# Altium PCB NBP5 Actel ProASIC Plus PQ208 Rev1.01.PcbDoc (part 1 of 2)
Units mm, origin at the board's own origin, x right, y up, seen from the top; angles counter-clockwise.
Board outline 69 x 80.99 mm, 2 copper layers (Top Layer, Bottom Layer); 65 components, 193 nets, 558 pads, 171 vias.
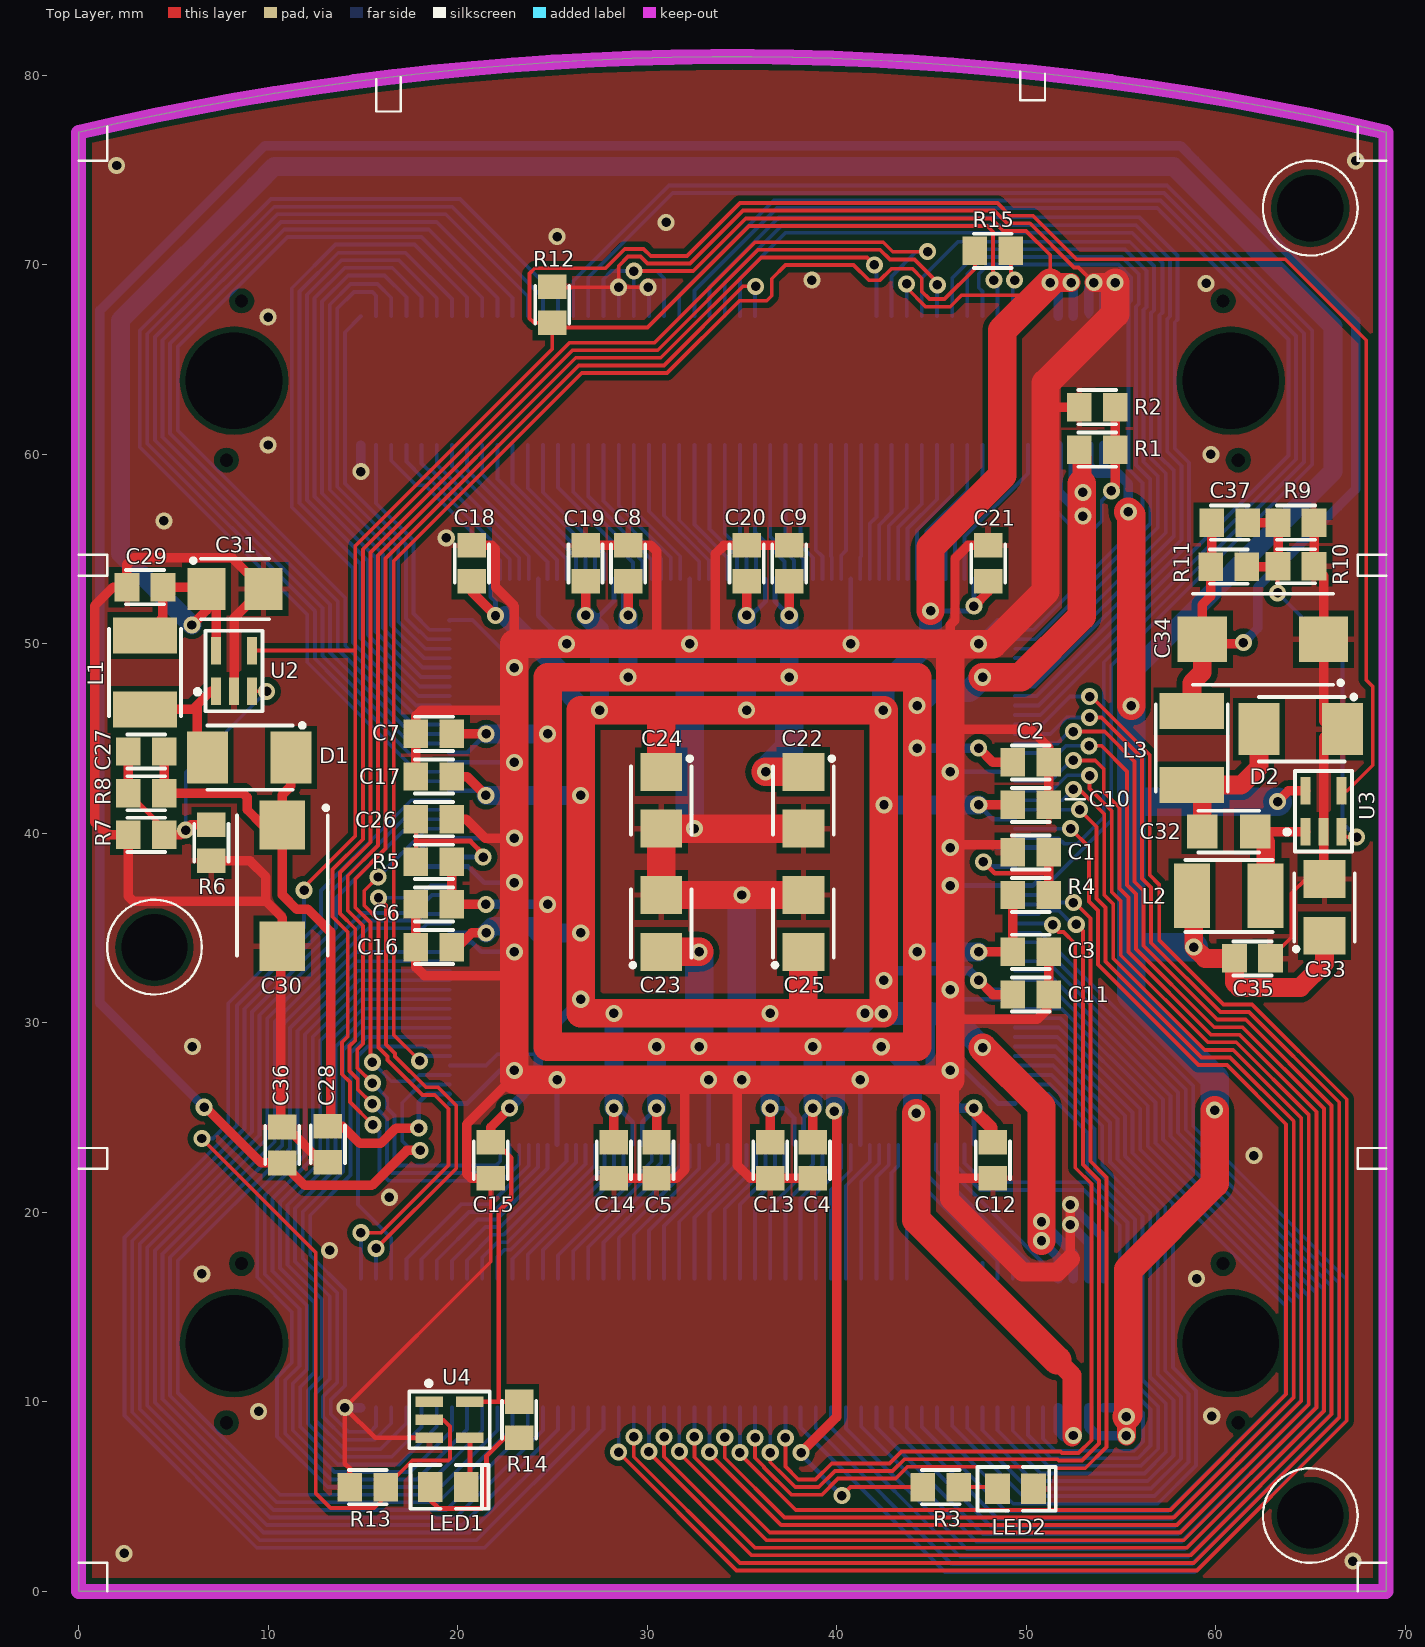
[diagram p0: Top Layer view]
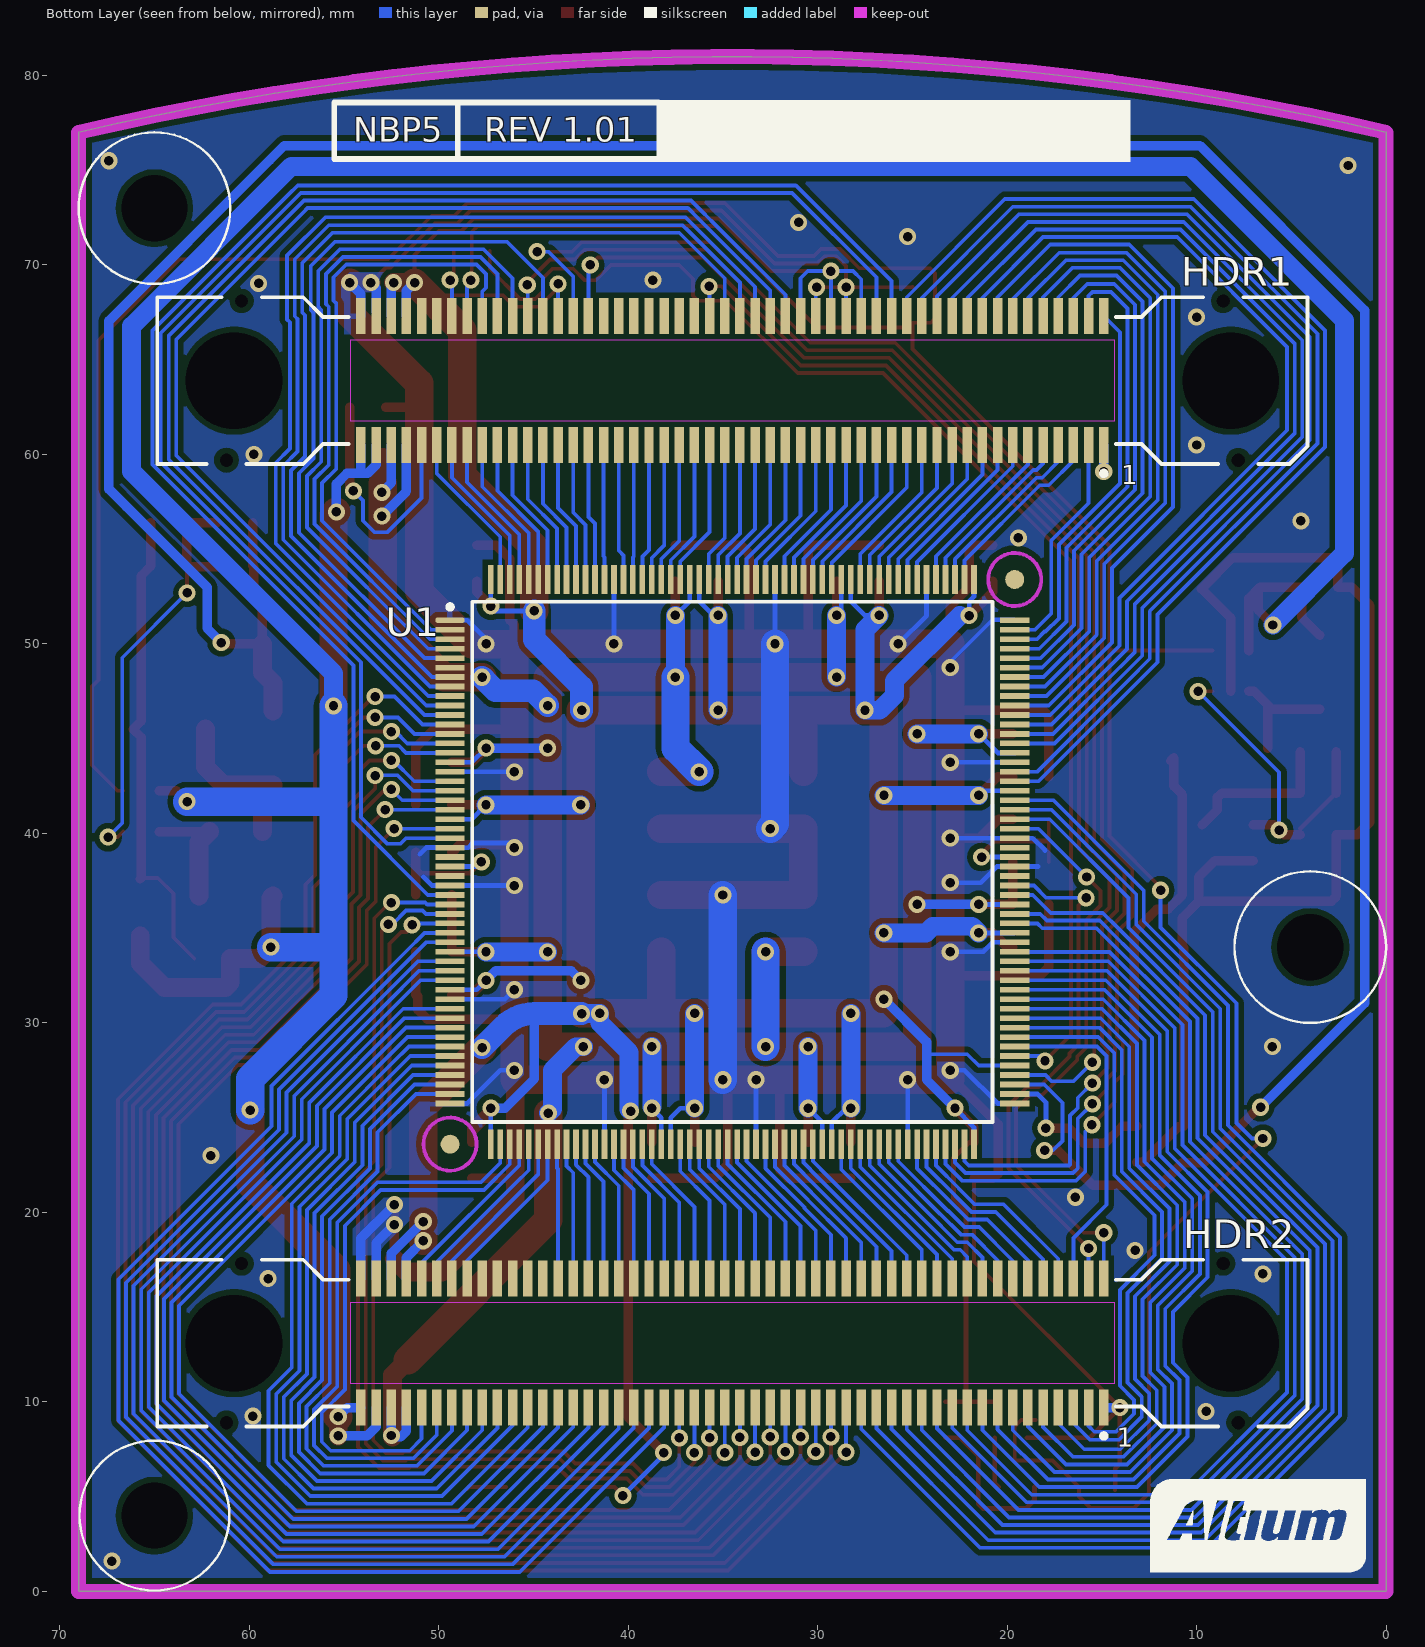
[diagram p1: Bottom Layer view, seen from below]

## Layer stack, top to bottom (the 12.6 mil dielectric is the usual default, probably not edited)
Top Layer: signal copper 0.0356
Dielectric: core 0.32, FR-4, Dk 4.8
Bottom Layer: signal copper 0.0356

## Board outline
0,0 0.001,77 cw(c34.5,-69.801) 69,77 69,0

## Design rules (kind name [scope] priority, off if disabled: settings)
Clearance Clearance_Polygons [InPolygon] p1: gap=0.3
Clearance [All] p2: gap=0.2
ComponentClearance [All] p1: gap=0.2 collisioncheckmode=3 verticalgap=0.254 showdistances=FALSE
FabricationTestPointUsage TestPointUsage [All] p1 off: valid=0 allowmultiple=FALSE
FabricationTestpoint Testpoint [All] p1 off: side=3 testpointundercomponent=TRUE minsize=1.016 maxsize=2.54 preferedsize=1.524 minholesize=0 maxholesize=1.016 preferedholesize=0.813 testpointgrid=0.025 allowsidetop=TRUE allowsidebottom=TRUE usegrid=TRUE gridtolerance=0
HoleSize [All] p1: absolutevalues=TRUE maxlimit=5.2 minlimit=0.25 maxpercent=80.000 minpercent=20.000
PlaneClearance [All] p1: clearance=0.5
PlaneConnect [All] p1: planeconnectstyle=Relief reliefexpansion=0.5 reliefentries=4 reliefconductorwidth=0.25 reliefairgap=0.25
PolygonConnect [All] p1: connectstyle=Relief reliefconductorwidth=0.3 reliefentries=4 polygonreliefangle="90 Angle"
RoomDefinition Actel_APA_1_01 [InComponentClass('Actel_APA_1_01')] p1 off: confinementstyle=ConfineIn formatcopy=TRUE lockcomponents=FALSE outline 3.9,7.7 3.9,69.1 65.2,69.1 65.2,7.7 51.98,4 21.98,4 17.25,4
RoutingVias [All] p1: holewidth=0.5 width=0.9 viastyle="Through Hole" minholewidth=0.3 minwidth=0.6 maxholewidth=0.5 maxwidth=0.9
SMDNeckDown [All] p1: percent=100.000
SilkscreenOverComponentPads [All] p1: minsilkscreentomaskgap=0.254
SolderMaskExpansion SolderMaskExpansion_Vias [IsVia] p1: expansion=-0.2
SolderMaskExpansion [All] p2: expansion=0.1
Width [All] p1: maxlimit=1.5 minlimit=0.2 preferedwidth=0.5
21 further rules are at their usual default settings.

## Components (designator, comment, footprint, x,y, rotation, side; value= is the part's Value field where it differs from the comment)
C1 "0.1uF" CC2012-0805 50.25,39 r180 top
C2 "0.1uF" CC2012-0805 50.25,43.75 r180 top
C3 "0.1uF" CC2012-0805 50.25,33.75 r180 top
C4 "0.1uF" CC2012-0805 38.75,22.75 r90 top
C5 "0.1uF" CC2012-0805 30.5,22.75 r90 top
C6 "0.1uF" CC2012-0805 18.75,36.25 r0 top
C7 "0.1uF" CC2012-0805 18.75,45.25 r0 top
C8 "0.1uF" CC2012-0805 29,54.25 r270 top
C9 "0.1uF" CC2012-0805 37.5,54.25 r270 top
C10 "0.1uF" CC2012-0805 50.25,41.5 r0 top
C11 "0.1uF" CC2012-0805 50.25,31.5 r180 top
C12 "0.1uF" CC2012-0805 48.25,22.75 r90 top
C13 "0.1uF" CC2012-0805 36.5,22.75 r90 top
C14 "0.1uF" CC2012-0805 28.25,22.75 r90 top
C15 "0.1uF" CC2012-0805 21.75,22.75 r90 top
C16 "0.1uF" CC2012-0805 18.75,34 r0 top
C17 "0.1uF" CC2012-0805 18.75,43 r0 top
C18 "0.1uF" CC2012-0805 20.75,54.25 r270 top
C19 "0.1uF" CC2012-0805 26.75,54.25 r270 top
C20 "0.1uF" CC2012-0805 35.25,54.25 r270 top
C21 "0.1uF" CC2012-0805 48,54.25 r270 top
C22 "10uF" MCCT-B 38.25,41.75 r270 top
C23 "10uF" MCCT-B 30.75,35.25 r90 top
C24 "10uF" MCCT-B 30.75,41.75 r270 top
C25 "10uF" MCCT-B 38.25,35.25 r90 top
C26 "0.1uF" CC2012-0805 18.75,40.75 r0 top
C27 "10pF" CC2012-0805 3.575,44.325 r180 top
C28 "0.1uF" CC2012-0805 13.15,23.6 r270 top
C29 "0.1uF" CC2012-0805 3.5,53 r180 top
C30 "22uF 25V" MCCT-D 10.75,37.25 r270 top
C31 "10uF" MCCT-B 8.25,52.9 r0 top
C32 "1uF 25V" CC3216-1206 60.7,40.1 r180 top
C33 "10uF" MCCT-B 65.75,36.1 r90 top
C34 "22uF" MCCT-D 62.5,50.25 r180 top
C35 "0.1uF" CC2012-0805 61.95,33.4 r0 top
C36 "0.1uF" CC2012-0805 10.75,23.559 r90 top
C37 "10pF" CC2012-0805 60.75,56.4 r0 top
D1 "MBRS140T3" 403A 9,44 r0 top
D2 "MBRS140T3" 403A 64.5,45.5 r0 top
HDR1 "54075-1009" 54075 34.5,63.9 r0 bottom locked
HDR2 "54075-1009" 54075 34.5,13.1 r0 bottom locked
L1 "10uH" CC4532-1812 3.5,48.5 r270 top
L2 "10uH" CC4532-1812 60.7,36.7 r0 top
L3 "10uH" CC4532-1812 58.75,44.5 r90 top
LED1 "HSMG-C170" "SMD _LED"#1 19.5,5.5 r180 top locked
LED2 "HSMH-C170" "SMD _LED"#2 49.442,5.408 r180 top locked
R1 "82R/1%" CC2012-0805 53.75,60.25 r0 top
R2 "680R/1%" CC2012-0805 53.75,62.5 r180 top
R3 "270R" CC2012-0805 45.5,5.5 r0 top
R4 "1R" CC2012-0805 50.25,36.75 r0 top
R5 "1R" CC2012-0805 18.75,38.5 r180 top
R6 "100K" CC2012-0805 7,39.5 r270 top
R7 "18K" CC2012-0805 3.575,39.925 r180 top
R8 "180K" CC2012-0805 3.575,42.125 r180 top
R9 "6k8" CC2012-0805 64.25,56.4 r0 top
R10 "1K2" CC2012-0805 64.25,54.1 r0 top
R11 "10K" CC2012-0805 60.7,54.075 r0 top
R12 "470R" CC2012-0805 25,67.9 r90 top
R13 "1K" CC2012-0805 15.25,5.5 r0 top
R14 "270R" CC2012-0805 23.25,9.05 r90 top
R15 "33R" CC2012-0805 48.25,70.75 r180 top
U1 "APA750-PQ208I" F-QFP28X28-G208/P.5N 34.49,38.49 r180 bottom locked
U2 "LT1930" SO-G5/P.95 7.25,47.5 r90 top
U3 "LT1931" SO-G5/P.95 64.75,40.1 r90 top
U4 "SN74LVC1G04DBV" SO-G5/P.95 18.5,10 r0 top

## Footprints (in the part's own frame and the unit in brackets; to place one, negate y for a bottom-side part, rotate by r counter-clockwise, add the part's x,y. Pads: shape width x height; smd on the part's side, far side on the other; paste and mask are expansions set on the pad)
403A [mm]
  rect 2.159x2.743 smd: 1(-2.2,0) 2(2.2,0)
  silkscreen extent -2.2,-1.7 2.9,1.8
54075 [mm] "Connector; Docking Station, Receptacle; 100 Position; Vertical"
  rect 0.5x1.9 smd: 1(-19.6,3.4) 2(-19.6,-3.4) 3(-18.8,3.4) 4(-18.8,-3.4) 5(-18,3.4) 6(-18,-3.4) 7(-17.2,3.4) 8(-17.2,-3.4) 9(-16.4,3.4) 10(-16.4,-3.4) 11(-15.6,3.4) 12(-15.6,-3.4) 13(-14.8,3.4) 14(-14.8,-3.4) 15(-14,3.4) 16(-14,-3.4) 17(-13.2,3.4) 18(-13.2,-3.4) 19(-12.4,3.4) 20(-12.4,-3.4) 21(-11.6,3.4) 22(-11.6,-3.4) 23(-10.8,3.4) 24(-10.8,-3.4) 25(-10,3.4) 26(-10,-3.4) 27(-9.2,3.4) 28(-9.2,-3.4) 29(-8.4,3.4) 30(-8.4,-3.4) 31(-7.6,3.4) 32(-7.6,-3.4) 33(-6.8,3.4) 34(-6.8,-3.4) 35(-6,3.4) 36(-6,-3.4) 37(-5.2,3.4) 38(-5.2,-3.4) 39(-4.4,3.4) 40(-4.4,-3.4) 41(-3.6,3.4) 42(-3.6,-3.4) 43(-2.8,3.4) 44(-2.8,-3.4) 45(-2,3.4) 46(-2,-3.4) 47(-1.2,3.4) 48(-1.2,-3.4) 49(-0.4,3.4) 50(-0.4,-3.4) 51(0.4,3.4) 52(0.4,-3.4) 53(1.2,3.4) 54(1.2,-3.4) 55(2,3.4) 56(2,-3.4) 57(2.8,3.4) 58(2.8,-3.4) 59(3.6,3.4) 60(3.6,-3.4) 61(4.4,3.4) 62(4.4,-3.4) 63(5.2,3.4) 64(5.2,-3.4) 65(6,3.4) 66(6,-3.4) 67(6.8,3.4) 68(6.8,-3.4) 69(7.6,3.4) 70(7.6,-3.4) 71(8.4,3.4) 72(8.4,-3.4) 73(9.2,3.4) 74(9.2,-3.4) 75(10,3.4) 76(10,-3.4) 77(10.8,3.4) 78(10.8,-3.4) 79(11.6,3.4) 80(11.6,-3.4) 81(12.4,3.4) 82(12.4,-3.4) 83(13.2,3.4) 84(13.2,-3.4) 85(14,3.4) 86(14,-3.4) 87(14.8,3.4) 88(14.8,-3.4) 89(15.6,3.4) 90(15.6,-3.4) 91(16.4,3.4) 92(16.4,-3.4) 93(17.2,3.4) 94(17.2,-3.4) 95(18,3.4) 96(18,-3.4) 97(18.8,3.4) 98(18.8,-3.4) 99(19.6,3.4) 100(19.6,-3.4)
  round 0.5 hole 0.7 unplated: MH1(-26.7,4.2) MH2(-25.9,-4.2) MH3(26.7,4.2) MH4(25.9,-4.2)
  round 4.8 hole 5.1 unplated: MH5(-26.3,0) MH6(26.3,0)
  Top Layer keep-out region: -20.15,2.15 20.15,2.15 20.15,-2.15 -20.15,-2.15
  silkscreen extent -30.35,-4.4 30.35,5.02
CC2012-0805 [mm]
  rect 1.3x1.5 smd: 1(-0.95,0.003) 2(0.95,0.003)
  silkscreen extent -1,-0.9 1,0.9
CC3216-1206 [mm]
  rect 1.6x1.8 smd: 1(-1.4,0) 2(1.4,0)
  silkscreen extent -1.6,-1.1 1.6,1.1
CC4532-1812 [mm]
  rect 1.9x3.4 smd: 1(-1.95,0) 2(1.95,0)
  silkscreen extent -2.3,-1.9 2.3,1.9
F-QFP28X28-G208/P.5N [mm]
  oval 1.55x0.3 smd: 1(-14.91,12.761)
  rect 1.55x0.3 smd: 2(-14.91,12.261) 3(-14.91,11.761) 4(-14.91,11.261) 5(-14.91,10.761) 6(-14.91,10.261) 7(-14.91,9.761) 8(-14.91,9.261) 9(-14.91,8.761) 10(-14.91,8.261) 11(-14.91,7.761) 12(-14.91,7.261) 13(-14.91,6.761) 14(-14.91,6.261) 15(-14.91,5.761) 16(-14.91,5.261) 17(-14.91,4.761) 18(-14.91,4.261) 19(-14.91,3.761) 20(-14.91,3.261) 21(-14.91,2.761) 22(-14.91,2.261) 23(-14.91,1.761) 24(-14.91,1.261) 25(-14.91,0.761) 26(-14.91,0.261) 27(-14.91,-0.239) 28(-14.91,-0.739) 29(-14.91,-1.239) 30(-14.91,-1.739) 31(-14.91,-2.239) 32(-14.91,-2.739) 33(-14.91,-3.239) 34(-14.91,-3.739) 35(-14.91,-4.239) 36(-14.91,-4.739) 37(-14.91,-5.239) 38(-14.91,-5.739) 39(-14.91,-6.239) 40(-14.91,-6.739) 41(-14.91,-7.239) 42(-14.91,-7.739) 43(-14.91,-8.239) 44(-14.91,-8.739) 45(-14.91,-9.239) 46(-14.91,-9.739) 47(-14.91,-10.239) 48(-14.91,-10.739) 49(-14.91,-11.239) 50(-14.91,-11.739) 51(-14.91,-12.239) 52(-14.91,-12.739) 105(14.89,-12.739) 106(14.89,-12.239) 107(14.89,-11.739) 108(14.89,-11.239) 109(14.89,-10.739) 110(14.89,-10.239) 111(14.89,-9.739) 112(14.89,-9.239) 113(14.89,-8.739) 114(14.89,-8.239) 115(14.89,-7.739) 116(14.89,-7.239) 117(14.89,-6.739) 118(14.89,-6.239) 119(14.89,-5.739) 120(14.89,-5.239) 121(14.89,-4.739) 122(14.89,-4.239) 123(14.89,-3.739) 124(14.89,-3.239) 125(14.89,-2.739) 126(14.89,-2.239) 127(14.89,-1.739) 128(14.89,-1.239) 129(14.89,-0.739) 130(14.89,-0.239) 131(14.89,0.261) 132(14.89,0.761) 133(14.89,1.261) 134(14.89,1.761) 135(14.89,2.261) 136(14.89,2.761) 137(14.89,3.261) 138(14.89,3.761) 139(14.89,4.261) 140(14.89,4.761) 141(14.89,5.261) 142(14.89,5.761) 143(14.89,6.261) 144(14.89,6.761) 145(14.89,7.261) 146(14.89,7.761) 147(14.89,8.261) 148(14.89,8.761) 149(14.89,9.261) 150(14.89,9.761) 151(14.89,10.261) 152(14.89,10.761) 153(14.89,11.261) 154(14.89,11.761) 155(14.89,12.261) 156(14.89,12.761)
  rect 0.3x1.55 smd: 53(-12.76,-14.889) 54(-12.26,-14.889) 55(-11.76,-14.889) 56(-11.26,-14.889) 57(-10.76,-14.889) 58(-10.26,-14.889) 59(-9.76,-14.889) 60(-9.26,-14.889) 61(-8.76,-14.889) 62(-8.26,-14.889) 63(-7.76,-14.889) 64(-7.26,-14.889) 65(-6.76,-14.889) 66(-6.26,-14.889) 67(-5.76,-14.889) 68(-5.26,-14.889) 69(-4.76,-14.889) 70(-4.26,-14.889) 71(-3.76,-14.889) 72(-3.26,-14.889) 73(-2.76,-14.889) 74(-2.26,-14.889) 75(-1.76,-14.889) 76(-1.26,-14.889) 77(-0.76,-14.889) 78(-0.26,-14.889) 79(0.24,-14.889) 80(0.74,-14.889) 81(1.24,-14.889) 82(1.74,-14.889) 83(2.24,-14.889) 84(2.74,-14.889) 85(3.24,-14.889) 86(3.74,-14.889) 87(4.24,-14.889) 88(4.74,-14.889) 89(5.24,-14.889) 90(5.74,-14.889) 91(6.24,-14.889) 92(6.74,-14.889) 93(7.24,-14.889) 94(7.74,-14.889) 95(8.24,-14.889) 96(8.74,-14.889) 97(9.24,-14.889) 98(9.74,-14.889) 99(10.24,-14.889) 100(10.74,-14.889) 101(11.24,-14.889) 102(11.74,-14.889) 103(12.24,-14.889) 104(12.74,-14.889) 157(12.74,14.911) 158(12.24,14.911) 159(11.74,14.911) 160(11.24,14.911) 161(10.74,14.911) 162(10.24,14.911) 163(9.74,14.911) 164(9.24,14.911) 165(8.74,14.911) 166(8.24,14.911) 167(7.74,14.911) 168(7.24,14.911) 169(6.74,14.911) 170(6.24,14.911) 171(5.74,14.911) 172(5.24,14.911) 173(4.74,14.911) 174(4.24,14.911) 175(3.74,14.911) 176(3.24,14.911) 177(2.74,14.911) 178(2.24,14.911) 179(1.74,14.911) 180(1.24,14.911) 181(0.74,14.911) 182(0.24,14.911) 183(-0.26,14.911) 184(-0.76,14.911) 185(-1.26,14.911) 186(-1.76,14.911) 187(-2.26,14.911) 188(-2.76,14.911) 189(-3.26,14.911) 190(-3.76,14.911) 191(-4.26,14.911) 192(-4.76,14.911) 193(-5.26,14.911) 194(-5.76,14.911) 195(-6.26,14.911) 196(-6.76,14.911) 197(-7.26,14.911) 198(-7.76,14.911) 199(-8.26,14.911) 200(-8.76,14.911) 201(-9.26,14.911) 202(-9.76,14.911) 203(-10.26,14.911) 204(-10.76,14.911) 205(-11.26,14.911) 206(-11.76,14.911) 207(-12.26,14.911) 208(-12.76,14.911)
  round 1 smd mask+1: FID1(-14.91,-14.889) FID2(14.89,14.911)
  Top Layer keep-out circle w0.2: c14.89,14.911 r1.4
  Top Layer keep-out circle w0.2: c-14.91,-14.889 r1.4
  silkscreen extent -15.03,-13.71 13.72,13.74
MCCT-B [mm]
  rect 2x2.2 smd: 1(-1.5,0) 2(1.5,0)
  silkscreen extent -2.3,-1.6 1.8,1.6
MCCT-D [mm]
  rect 2.6x2.4 smd: 1(-3.2,0) 2(3.2,0)
  silkscreen extent -4.2,-2.4 3.7,2.4
"SMD _LED"#1 [mm]
  rect 1.3x1.6 smd: 1(0.943,-0.012) 2(-0.957,-0.012)
  silkscreen extent -2.14,-1.16 1.99,1.14
"SMD _LED"#2 [mm]
  rect 1.3x1.6 smd: 1(0.95,0) 2(-0.95,0)
  silkscreen extent -2.13,-1.15 2,1.15
SO-G5/P.95 [mm]
  rect 1.45x0.55 smd: 1(0,0) 2(0,-0.95) 3(0,-1.9) 4(2.15,-1.9) 5(2.15,0)
  silkscreen extent -1.05,-2.45 3.2,1.1

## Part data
C1 C2 C3 C4 C5 C6 C7 C8 C9 C10 C11 C12 C13 C14 C15 C16 C17 C18 C19 C20 C21 C26 C27 C28 C29 C32 C35 C36 C37: library part CAP, "Capacitor"
C22 C23 C24 C25 C30 C31 C33 C34: library part CAP_POLAR, "Polar Capacitor"
D1 D2: library part Shottky, "Shottky Diode"
HDR1 HDR2: "Board-to-Board, Docking Station, 0.80mm (.031\") Pitch, Shielded Receptacle, Vertical, Ultra Low Profile, SMT"
L1 L2 L3: library part INDUCTOR, "Inductor"
LED1 LED2: library part HSMX-C670, "Typical RED GaAs SMD LED Agilent make"
R1 R2 R3 R4 R5 R6 R7 R8 R9 R10 R11 R12 R13 R14 R15: library part RES, "Resistor"
U1: "ProASICPlus APA750 Flash FPGA, 156 User IOs, 208-Pin PQFP, Speed Grade Standard, Industrial Grade"
U2 U3: "Switching Regulator"
U4: library part SN74AHC1G04DBVR

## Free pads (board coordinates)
  round 3.2 hole 3.5 unplated: LP(4,34) LP(65,4) LP(65,73)

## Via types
v1: diameter 0.9, hole 0.5, Top Layer to Bottom Layer, tented bottom, 171 vias

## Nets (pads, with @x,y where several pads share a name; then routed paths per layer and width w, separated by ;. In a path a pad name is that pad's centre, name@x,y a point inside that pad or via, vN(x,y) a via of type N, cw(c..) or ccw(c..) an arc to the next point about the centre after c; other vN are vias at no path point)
5V: C29.1 C31.1 C33.1 C35.1 HDR1.97 HDR1.99 HDR2.97 HDR2.99 L1.1 L2.1 U2.5 U3.5 | length 213.5
  Top Layer w0.5: L1.1@3.5,50.45 4.45,51.4 C29.1@4.45,52.997 6.653,52.997 7.25,52.4 U2.5@7.25,49.65 ; v1(5.975,51) 6.75,51.775 C31.1@6.75,52.9 ; v1(63.275,41.675) 63.85,42.25 U3.5@64.75,42.25
  Top Layer w1: v1(55.3,8.2) v1(55.3,9.225) ; L2.1@58.75,36.7 58.85,36.6 v1(58.85,34) 59.447,33.403 C35.1@61,33.403 61,32.125 61.25,31.875 64.475,31.875 65.75,33.15 C33.1@65.75,34.6
  Top Layer w1.5: v1(55.3,9.225) 55.4,9.325 55.4,16.975 59.95,21.525 v1(59.95,25.4) ; v1(55.4,56.975) 55.55,56.825 v1(55.55,46.735)
  Bottom Layer w0.5: HDR2.97@53.3,9.7 53.3,8.675 53.775,8.2 v1(55.3,8.2) ; HDR1.97@53.3,60.5 53.3,59.45 53.75,59 54.85,59 55.4,58.45 v1(55.4,56.975) ; HDR2.99@54.1,9.7 54.825,9.7 v1(55.3,9.225) ; HDR1.99@54.1,60.5 54.1,59.125 54.225,59
  Bottom Layer w1: v1(5.975,51) 2.2,54.775 2.2,67.075 9.315,74.19 10.325,75.2 57.775,75.2 66.2,66.775 66.2,59.1 55.55,48.45 v1(55.55,46.735)
  Bottom Layer w1.5: 55.55,34 v1(58.85,34) ; v1(55.55,46.735) 55.55,31.45 59.95,27.05 v1(59.95,25.4) ; 55.725,41.675 v1(63.275,41.675)
AUDIO_SPI_CSN: HDR1.11 U1.161 | length 9.1
  Bottom Layer w0.2: HDR1.11@18.9,60.5 18.9,59.475 23.75,54.625 U1.161@23.75,53.425
AVDD1: C1.1 R4.2 U1.27 | length 8.1
  Top Layer w0.25: v1(47.75,38.5) 48.35,37.9 50.9,37.9 51,38 C1.1@51.35,38.375
  Top Layer w0.5: R4.2@51.2,36.753 C1.1@51.2,38.997
  Bottom Layer w0.25: v1(47.75,38.5) 48,38.25 U1.27@49.425,38.25
AVDD2: C26.1 R5.2 U1.131 | length 8
  Top Layer w0.2: R5.2@17.8,38.497 C26.1@17.8,40.753
  Top Layer w0.25: 17.8,39.6 20.675,39.6 21.1,39.175 21.1,39 v1(21.35,38.75)
  Bottom Layer w0.25: U1.131@19.6,38.751 v1(21.35,38.75)
BLUE0: HDR1.14 U1.148 | length 36.4
  Bottom Layer w0.2: U1.148@19.575,47.25 17.925,47.25 14.869,50.306 14.869,54.215 11.65,57.434 11.65,68.6 13.7,70.65 17.25,70.65 19.7,68.2 HDR1.14@19.7,67.3
BLUE1: HDR1.16 U1.147 | length 38.9
  Bottom Layer w0.2: U1.147@19.575,46.75 17.8,46.75 14.469,50.081 14.469,54.006 11.25,57.225 11.25,68.775 13.55,71.075 17.725,71.075 20.5,68.3 HDR1.16@20.5,67.3
BOC_CTS: HDR1.13 U1.163 | length 9.2
  Bottom Layer w0.2: HDR1.13@19.7,60.5 19.7,59.375 24.75,54.325 U1.163@24.75,53.425
BOC_RTS: HDR1.17 U1.165 | length 8.9
  Bottom Layer w0.2: HDR1.17@21.3,60.5 21.3,58.941 25.75,54.491 U1.165@25.75,53.425
BOC_RX: HDR1.19 U1.166 | length 8.8
  Bottom Layer w0.2: HDR1.19@22.1,60.5 22.1,58.706 26.25,54.556 U1.166@26.25,53.425
BOC_TX: HDR1.15 U1.164 | length 9
  Bottom Layer w0.2: HDR1.15@20.5,60.5 20.5,59.175 25.25,54.425 U1.164@25.25,53.425
BUZZER: HDR2.24 U1.91 | length 9
  Bottom Layer w0.2: HDR2.24@23.7,16.5 23.7,17.775 28.25,22.325 U1.91@28.25,23.575
CAN_RXD: HDR1.4 U1.153 | length 24.7
  Bottom Layer w0.2: HDR1.4@15.7,67.3 15.7,68.375 15.5,68.575 14.525,68.575 13.65,67.7 13.65,58.3 16.869,55.081 16.869,51.181 18.3,49.75 U1.153@19.575,49.75
CAN_TXD: HDR1.2 U1.154 | length 20.4
  Bottom Layer w0.2: HDR1.2@14.9,67.3 14.05,66.45 14.05,58.475 17.269,55.256 17.269,51.346 17.966,50.65 18.025,50.65 18.425,50.25 U1.154@19.575,50.25
FPGA_AUX0: HDR1.86 R12.1 R13.2 U2.4 U3.4 U4.2 | length 197.7
  Top Layer w0.2: v1(6.5,23.9) 12.508,17.892 12.508,5.192 13.3,4.4 15.6,4.4 16.2,5 R13.2@16.2,5.503 17.605,6.907 19.507,6.907 19.6,7 19.6,8.7 19.25,9.05 U4.2@18.5,9.05 ; U2.4@9.15,49.65 14.55,49.65 ; v1(11.9,37) 11.9,37.163 14.6,39.863 14.6,55.166 24.997,65.563 R12.1@24.997,66.95 ; v1@48.25,69.25 v1(48.3,69.2) ; 48.25,69.65 48.25,71.75 47.95,72.05 35.375,72.05 30.025,66.7 25.247,66.7 R12.1@24.997,66.95 ; U3.4@66.65,42.25 66.95,42.25 68.3,43.6 68.3,47.75 67.95,48.1 67.95,66.025 63.675,70.3 52.666,70.3 50.366,72.6 49.166,72.6 48.491,73.275 34.9,73.275 32.1,70.475 30.191,70.475 29.816,70.85 28.825,70.85 27.8,69.825 24.075,69.825 23.8,69.55 23.8,67.175 24.025,66.95 R12.1@24.997,66.95
  Bottom Layer w0.2: v1(6.5,23.9) 7.084,23.9 7.9,24.716 7.9,31.041 11.9,35.041 v1(11.9,37) ; v1(48.3,69.2) 48.5,69 HDR1.86@48.5,67.3 48.5,68.3
FPGA_AUX1: HDR1.88 R15.1 | length 7.1
  Top Layer w0.2: v1@49.1,69.2 49.2,69.3 R15.1@49.2,70.747 49.2,69.4 v1(49.4,69.2)
  Bottom Layer w0.2: v1@49.1,69.2 49.3,69 HDR1.88@49.3,67.3 49.3,69.1 v1(49.4,69.2)
FPGA_AUX2: HDR1.90
FPGA_AUX3: HDR1.92
FPGA_CCLK: HDR1.66
FPGA_CLK: HDR2.2 U1.134 | length 31.1
  Top Layer w0.2: v1(14.9,18.925) 15.959,18.925 19.525,22.491 19.525,25.469 18.794,26.2 18.15,26.2 16.3,28.05 16.3,28.225 15.825,28.7 15.825,35.438 15.075,36.188 15.075,36.975 v1(15.8,37.7)
  Bottom Layer w0.2: HDR2.2@14.9,16.5 v1(14.9,18.925) ; v1(15.8,37.7) 18.351,40.251 U1.134@19.6,40.251
FPGA_CLK_1: HDR1.30 U1.30 | length 83.1
  Bottom Layer w0.2: HDR1.30@26.1,67.3 26.1,69.15 30.432,73.482 31.15,74.2 57.441,74.2 57.944,73.696 57.954,73.696 65.1,66.55 65.1,59.469 54.5,48.869 54.5,40.675 50.575,36.75 U1.30@49.425,36.75
FPGA_CLK_2: HDR1.32 U1.24 | length 80
  Bottom Layer w0.2: HDR1.32@26.9,67.3 26.9,69.35 31.35,73.8 57.275,73.8 64.675,66.4 64.675,59.609 54.1,49.034 54.1,40.85 52.7,39.45 52.025,39.45 51.725,39.75 U1.24@49.425,39.75
FPGA_DIN: HDR1.64
FPGA_INIT: HDR1.68
FPGA_M0: HDR1.60
FPGA_M1: HDR1.58
FPGA_M2: HDR1.56
FPGA_PROGRAM: HDR1.62
FPGA_RCK: R15.2 U1.110 | length 69.6
  Top Layer w0.2: v1(18,28) 16.625,29.375 16.625,54.362 26.556,64.294 31.05,64.294 34.872,68.116 36.316,68.116 36.575,68.375 36.575,69.275 37.3,70 40.9,70 41.7,69.2 42.3,69.2 42.9,69.8 44,69.8 44.5,69.3 44.5,68.6 44.9,68.2 45.7,68.2 47.3,69.8 R15.2@47.3,70.747
  Bottom Layer w0.2: v1(18,28) 18.251,28.251 U1.110@19.6,28.251
FPGA_TCK: HDR1.72 U1.101 | length 85
  Top Layer w0.2: v1(15.525,24.625) 14.319,25.831 14.319,26.874 13.9,27.294 13.9,28.975 14.2,29.275 14.2,34.8 13.4,35.6 13.4,38.097 15,39.697 15,55 25.9,65.9 30.394,65.9 35.694,71.2 42.466,71.2 42.966,70.7 v1(44.8,70.7)
  Bottom Layer w0.2: v1(15.525,24.625) 15.875,24.275 15.875,22.15 16.35,21.675 22.375,21.675 23.25,22.55 U1.101@23.25,23.575 ; HDR1.72@42.9,67.3 42.9,69.4 44.2,70.7 v1(44.8,70.7)
FPGA_TDI: HDR1.78 U1.102 | length 81.5
  Top Layer w0.2: v1(15.5,25.725) 14.725,26.5 14.725,27.034 14.3,27.459 14.3,28.775 14.6,29.075 14.6,34.966 13.8,35.766 13.8,37.931 15.4,39.531 15.4,54.834 26.066,65.5 30.559,65.5 35.859,70.8 42.3,70.8 42.817,70.283 44.117,70.283 45.325,69.075 v1(45.325,68.95) v1@45.125,68.75
  Bottom Layer w0.2: v1(15.5,25.725) 16.275,24.95 16.275,22.325 16.525,22.075 22.2,22.075 22.75,22.625 U1.102@22.75,23.575 ; HDR1.78@45.3,67.3 45.3,68.925 v1(45.325,68.95)
FPGA_TDO: HDR1.54 U1.108 | length 59.3
  Top Layer w0.2: v1(15.5,27.925) 15.4,28.025 15.4,35.297 14.6,36.097 14.6,37.6 16.2,39.2 16.2,54.503 26.397,64.7 30.891,64.7 35.066,68.875 v1(35.725,68.875)
  Bottom Layer w0.2: v1(15.5,27.925) 16.5,26.925 17.65,26.925 17.975,27.25 U1.108@19.575,27.25 ; HDR1.54@35.7,67.3 v1@35.7,68.85
FPGA_TMS: HDR1.70 U1.103 | length 76.5
  Top Layer w0.2: v1(15.5,26.825) 14.7,27.625 14.7,28.6 15,28.9 15,35.131 14.2,35.931 14.2,37.766 15.8,39.366 15.8,54.669 26.231,65.1 30.725,65.1 36.025,70.4 41.6,70.4 v1(42,70)
  Bottom Layer w0.2: v1(15.5,26.825) 16.275,26.05 16.275,25.516 16.675,25.116 16.675,22.525 16.725,22.475 22.025,22.475 22.25,22.7 U1.103@22.25,23.575 ; v1(42,70) 42.1,70.1 HDR1.70@42.1,67.3
GND: C1.2 C2.1 C3.1 C4.1 C5.1 C6.1 C7.1 C8.1 C9.1 C10.2 C11.1 C12.1 C13.1 C14.1 C15.1 C16.1 C17.1 C18.1 C19.1 C20.1 C21.1 C22.2 C23.2 C24.2 C25.2 C26.2 C28.2 C29.2 C30.2 C31.2 C33.2 C34.1 C35.2 C36.2 D2.2 HDR1.1 HDR1.36 HDR1.40 HDR1.98 HDR1.100 HDR2.1 HDR2.98 HDR2.100 LED2.2 R2.2 R6.2 R7.2 R9.2 R10.2 R12.2 R13.1 U1.1 U1.17 U1.25 U1.29 U1.41 U1.52 U1.65 U1.81 U1.97 U1.105 U1.122 U1.130 U1.133 U1.141 U1.156 U1.162 U1.178 U1.195 U2.2 U3.2 U4.3 | length 509.2
  Top Layer w0.2: v1(14.05,9.7) 21.747,17.397 C15.1@21.747,21.8 ; R13.1@14.3,5.35 R13.1@14.3,5.503 ; R12.2@24.997,68.85 25.022,68.825 v1(30.05,68.825) ; v1(28.5,68.825) 28.5,69.95 29,70.45 29.65,70.45 30.025,70.075 32.269,70.075 35.069,72.875 48.325,72.875 49,72.2 50.2,72.2 52.525,69.875 52.775,69.875 v1(53.575,69.075) ; C35.2@62.9,33.403 64,34.503 64,36.825 64.825,37.65 C33.2@65.7,37.65
  Top Layer w0.25: R13.1@14.3,5.503 14.3,6.497 14.05,6.747 v1(14.05,9.7) 15.65,8.1 U4.3@18.95,8.1
  Top Layer w0.5: R7.2@2.625,39.872 2.625,36.675 2.875,36.425 9.875,36.425 ; R7.2@2.625,39.922 1.528,39.922 0.85,40.6 0.85,52.025 1.822,52.997 C29.2@2.55,52.997 2.55,54.2 2.9,54.55 8.1,54.55 C31.2@9.75,52.9 9.725,52.9 8.2,51.375 U2.2@8.2,47.5 ; R6.2@7.003,38.55 9.05,38.55 9.875,37.725 9.875,36.425 ; C28.2@13.153,22.65 12.825,22.65 10.966,24.509 C36.2@10.747,24.509 10.675,24.582 10.675,33.975 C30.2@10.75,34.05 10.75,35.55 9.875,36.425 ; C6.1@17.8,36.253 17.8,32.95 18.25,32.5 23,32.5 ; C17.1@17.8,43.003 17.8,46.2 18.1,46.5 23,46.5 ; C26.2@19.7,40.753 20.447,40.753 21.45,39.75 v1(23,39.75) ; C18.1@20.753,55.2 21.8,55.2 22,55 22,53 23,52 23,50 ; C15.1@21.747,21.8 20.725,21.8 20.475,22.05 20.475,24.65 22.825,27 23,27 ; C19.1@26.753,55.2 30.2,55.2 30.5,54.9 30.5,50 ; C14.1@28.247,21.8 31.55,21.8 32,22.25 32,27 ; 33.75,50 33.6,50.15 33.6,54.75 34.05,55.2 C9.1@37.503,55.2 ; v1@34.75,27 34.75,22.5 35.45,21.8 C4.1@38.747,21.8 ; v1(46,39.25) 46.15,39.4 48.898,39.4 C1.2@49.3,38.997 ; 46,45.5 50.25,45.5 51.2,44.55 C10.2@51.2,41.503 ; 46,50 46,51 46.25,51.25 46.25,54.5 46.95,55.2 C21.1@48.003,55.2 ; 46.008,21.8 C12.1@48.247,21.8 ; 46.05,30.2 50.6,30.2 51.1,30.7 51.1,31.397 C11.1@51.2,31.497 C3.1@51.2,33.747 ; 51.025,62.5 51.028,62.497 R2.2@52.8,62.497 ; 52.339,17.537 v1(52.339,20.407) ; R9.2@65.2,56.403 R10.2@65.2,54.103 65.7,53.602 65.7,45.925 66.125,45.5 65.7,45.075 65.7,37.65 C33.2@65.75,37.6
  Top Layer w1: 45.958,26.992 45.958,20.707 49.815,16.85 51.652,16.85 52.339,17.537 ; v1(53.575,69.075) v1(54.7,69.075)
  Top Layer w1.5: C25.2@38.25,36.75 C23.2@30.75,36.75 C24.2@30.75,40.25 C22.2@38.25,40.25 ; 45.958,49.992 48.25,49.992 51.025,52.767 51.025,63.75 54.701,67.418 v1(54.7,69.075) ; 23,27 46,27 46,50 23,50 23,27
  Bottom Layer w0.2: U1.156@19.61,51.261 20.789,51.261 23,49.05 v1(23,48.75) ; HDR1.36@28.5,67.3 v1(28.5,68.825) ; HDR1.40@30.1,67.3 v1@30.1,68.775
  Bottom Layer w0.25: 18,39.1 18.651,39.751 U1.133@19.6,39.751 ; 18.351,38.251 U1.130@19.6,38.251 ; U1.105@19.575,25.75 20.5,25.75 22.25,27.5 v1(23,27.5) ; U1.122@19.575,34.25 20.75,34.25 21.25,33.75 v1(23,33.75) ; U1.130@19.575,38.25 20.55,38.25 21.4,37.4 v1(23,37.4) ; U1.133@19.575,39.75 v1(23,39.75) ; U1.141@19.575,43.75 v1(23,43.75) ; U1.156@19.575,51.25 U1.156@19.61,51.25 ; U1.162@24.25,53.425 24.25,51.5 v1(25.75,50) ; U1.97@25.25,23.575 v1(25.25,27) ; v1(32.25,50) U1.178@32.25,53.425 ; U1.81@33.25,23.575 v1(33.25,27) ; v1(40.75,50) U1.195@40.75,53.425 ; U1.65@41.25,23.575 v1(41.25,27) ; v1(46,27.5) 46.75,27.5 48.5,25.75 U1.52@49.425,25.75 ; v1(46,31.75) 46.5,31.25 U1.41@49.425,31.25 ; v1(46,37.25) U1.29@49.425,37.25 ; v1(46,39.25) 46.25,39.5 48.2,39.5 48.45,39.25 U1.25@49.425,39.25 ; v1(46,43.25) U1.17@49.425,43.25 ; v1(47.5,50) 47.5,50.25 48.5,51.25 U1.1@49.425,51.25 ; U1.29@49.4,37.251 50.351,37.251 50.8,37.7 ; U1.25@49.4,39.251 50.649,39.251 51,38.9 ; HDR1.98@53.3,67.3 HDR1.98@53.3,67.5
  Bottom Layer w0.5: v1(14.05,9.7) HDR2.1@14.9,9.7 ; v1(14.9,59.1) HDR1.1@14.9,60.5 ; v1(52.339,19.357) 53.3,18.396 HDR2.98@53.3,16.5 ; v1(52.339,20.407) 54.1,18.646 HDR2.100@54.1,16.5 ; HDR1.98@53.3,67.5 53.3,68.8 v1(53.575,69.075) ; HDR1.100@54.1,67.3 54.1,68.475 v1(54.7,69.075)
  Bottom Layer w1.5: v1(32.25,50) 32.25,40.5 v1(32.5,40.25) ; v1(35,27) v1(35,36.75)
  other v1: 67.25,1.6 2.4,2 59.8,9.25 9.5,9.5 59,16.5 6.5,16.75 13.25,18 16.4,20.8 62.025,23 6,28.75 19.4,55.6 4.5,56.5 59.75,60 10,60.5 10,67.25 59.5,69.025 38.7,69.2 25.25,71.5 31,72.25 2,75.25 67.4,75.5
GREEN0: HDR1.10 U1.150 | length 31.8
  Bottom Layer w0.2: HDR1.10@18.1,67.3 18.1,68.3 16.55,69.85 14.05,69.85 12.45,68.25 12.45,57.784 15.669,54.565 15.669,50.656 18.075,48.25 U1.150@19.575,48.25
GREEN1: HDR1.12 U1.149 | length 34.1
  Bottom Layer w0.2: HDR1.12@18.9,67.3 18.9,68.25 16.9,70.25 13.875,70.25 12.05,68.425 12.05,57.6 15.269,54.381 15.269,50.481 18,47.75 U1.149@19.575,47.75
HDRIVE: HDR1.18 U1.146 | length 47.2
  Bottom Layer w0.2: U1.146@19.575,46.25 17.725,46.25 14.069,49.906 14.069,52.431 5.225,61.275 5.225,65.675 11.025,71.475 18.1,71.475 21.3,68.275 HDR1.18@21.3,67.3
IO0: HDR2.7 U1.114 | length 35.1
  Bottom Layer w0.2: HDR2.7@17.3,9.7 17.3,8.875 15.925,7.5 14.025,7.5 12.5,9.025 12.5,10.45 13.25,11.2 13.25,15.578 11.425,17.403 11.425,20.2 13.55,22.325 13.55,28.743 15.057,30.25 U1.114@19.575,30.25
IO1: HDR2.9 U1.115 | length 37.6
  Bottom Layer w0.2: HDR2.9@18.1,9.7 18.1,8.675 16.525,7.1 13.85,7.1 12.1,8.85 12.1,10.616 12.85,11.366 12.85,15.413 11.025,17.238 11.025,20.375 13.15,22.5 13.15,28.909 14.991,30.75 U1.115@19.575,30.75
IO2: HDR2.11 U1.116 | length 39.9
  Bottom Layer w0.2: HDR2.11@18.9,9.7 18.9,8.7 16.9,6.7 13.675,6.7 11.7,8.675 11.7,10.8 12.45,11.55 12.45,15.247 10.625,17.072 10.625,20.55 12.75,22.675 12.75,29.075 14.925,31.25 U1.116@19.575,31.25
IO3: HDR2.13 U1.117 | length 42.4
  Bottom Layer w0.2: U1.117@19.575,31.75 14.86,31.75 12.35,29.24 12.35,22.85 10.225,20.725 10.225,16.906 12.05,15.081 12.05,11.716 11.3,10.966 11.3,8.5 13.5,6.3 17.5,6.3 19.7,8.5 HDR2.13@19.7,9.7
IO4: HDR2.15 U1.118 | length 44.7
  Bottom Layer w0.2: U1.118@19.575,32.25 14.794,32.25 11.95,29.406 11.95,23.025 9.825,20.9 9.825,16.741 11.65,14.916 11.65,11.9 10.9,11.15 10.9,8.325 13.325,5.9 17.85,5.9 20.5,8.55 HDR2.15@20.5,9.7
IO5: HDR2.17 U1.119 | length 47.1
  Bottom Layer w0.2: U1.119@19.575,32.75 14.728,32.75 11.55,29.572 11.55,23.2 9.425,21.075 9.425,16.575 11.25,14.75 11.25,12.066 10.475,11.291 10.475,8.175 13.15,5.5 18.3,5.5 21.3,8.5 HDR2.17@21.3,9.7
IO6: HDR2.19 U1.120 | length 53.3
  Bottom Layer w0.2: U1.120@19.575,33.25 14.663,33.25 11.15,29.737 11.15,23.375 5.225,17.45 5.225,14.975 5.225,10.5 10.625,5.1 18.7,5.1 22.1,8.5 HDR2.19@22.1,9.7
IO7: HDR2.21 U1.121 | length 55.6
  Bottom Layer w0.2: U1.121@19.575,33.75 14.597,33.75 10.75,29.903 10.75,23.559 4.825,17.634 4.825,10.325 10.45,4.7 18.975,4.7 22.9,8.625 HDR2.21@22.9,9.7
IO8: HDR2.23 U1.124 | length 58.3
  Bottom Layer w0.2: U1.124@19.6,35.251 18.401,35.251 18.15,35 15.281,35 10.35,30.069 10.35,23.725 4.425,17.8 4.425,10.15 10.275,4.3 19.4,4.3 23.7,8.6 HDR2.23@23.7,9.7
IO9: HDR2.25 U1.125 | length 60.7
  Bottom Layer w0.2: U1.125@19.6,35.751 18.251,35.751 17.9,35.4 15.116,35.4 14.266,34.55 13.616,33.9 9.95,30.234 9.95,23.909 4.025,17.984 4.025,9.975 10.1,3.9 19.9,3.9 24.5,8.5 HDR2.25@24.5,9.7
IO10: HDR2.27 U1.127 | length 63.3
  Bottom Layer w0.2: U1.127@19.6,36.751 18.651,36.751 17.7,35.8 14.95,35.8 14.125,34.975 9.55,30.4 9.55,24.075 3.625,18.15 3.625,9.8 9.925,3.5 20.25,3.5 25.3,8.55 HDR2.27@25.3,9.7
IO11: HDR2.29 U1.135 | length 68
  Bottom Layer w0.2: U1.135@19.6,40.751 17.751,40.751 13.588,36.588 13.588,35.022 9.15,30.584 9.15,24.259 3.225,18.334 3.225,9.625 9.75,3.1 20.625,3.1 26.1,8.575 HDR2.29@26.1,9.7
IO12: HDR2.31 U1.136 | length 70.5
  Bottom Layer w0.2: U1.136@19.6,41.251 17.651,41.251 13.188,36.788 13.188,35.188 8.75,30.75 8.75,24.425 2.825,18.5 2.825,16.025 2.825,9.45 9.575,2.7 21,2.7 26.9,8.6 HDR2.31@26.9,9.7 ; U1.136@19.6,41.3 U1.136@19.8,41.3
IO13: HDR2.33 U1.137 | length 72.7
  Bottom Layer w0.2: U1.137@19.6,41.751 17.551,41.751 12.788,36.988 12.788,35.363 8.35,30.925 8.35,24.6 2.425,18.675 2.425,9.275 9.4,2.3 21.425,2.3 27.7,8.575 HDR2.33@27.7,9.7
IO14: HDR2.35 U1.12 | length 96
  Top Layer w0.2: v1(28.5,7.35) 28.5,7.325 34.725,1.1 59.025,1.1 66.925,9 66.925,25.975 61.924,30.976 60.425,30.976 57.025,34.375 57.025,37.3 56.525,37.8 56.525,44.141 54.285,46.38 53.441,47.225 v1(53.35,47.225)
  Bottom Layer w0.2: v1(28.5,7.35) HDR2.35@28.5,9.7 ; U1.12@49.4,45.751 50.851,45.751 52.325,47.225 v1(53.35,47.225)
IO15: HDR2.37 U1.13 | length 93.3
  Top Layer w0.2: v1(29.3,8.15) 29.3,7.1 34.9,1.5 58.85,1.5 66.525,9.175 66.525,25.809 61.759,30.575 60.26,30.575 56.6,34.235 56.6,37.141 56.125,37.616 56.125,43.975 53.975,46.125 v1(53.35,46.125)
  Bottom Layer w0.2: v1(29.3,8.15) HDR2.37@29.3,9.7 ; U1.13@49.4,45.251 51.276,45.251 52.15,46.125 v1(53.35,46.125)
IO16: HDR2.39 U1.14 | length 90.4
  Top Layer w0.2: v1(30.1,7.375) 30.1,7.325 35.525,1.9 58.675,1.9 66.125,9.35 66.125,25.643 61.593,30.175 60.094,30.175 56.2,34.069 56.2,36.975 55.725,37.45 55.725,43.8 54.15,45.375 v1(52.5,45.375)
  Bottom Layer w0.2: v1(30.1,7.375) HDR2.39@30.1,9.7 ; U1.14@49.4,44.751 51.661,44.751 v1@52.284,45.375
IO17: HDR2.41 U1.15 | length 88
  Top Layer w0.2: v1(30.9,8.15) 30.9,7.1 35.7,2.3 58.5,2.3 65.725,9.525 65.725,25.478 61.428,29.775 59.928,29.775 59.646,30.057 55.8,33.903 55.8,36.8 55.325,37.275 55.325,43.275 53.975,44.625 v1(53.325,44.625)
  Bottom Layer w0.2: v1(30.9,8.15) HDR2.41@30.9,9.7 ; U1.15@49.4,44.251 51.726,44.251 52.1,44.625 v1(53.325,44.625)
IO18: HDR2.43 U1.18 | length 85.4
  Top Layer w0.2: v1(31.7,7.375) 31.7,7.3 36.3,2.7 58.325,2.7 65.325,9.7 65.325,25.312 61.262,29.375 59.763,29.375 55.4,33.738 55.4,36.625 54.925,37.1 54.925,41.356 54.1,42.181 54.1,43.4 53.65,43.85 v1(52.5,43.85)
  Bottom Layer w0.2: v1(31.7,7.375) HDR2.43@31.7,9.7 ; U1.18@49.4,42.751 51.286,42.751 52.384,43.85 v1(52.5,43.85)
IO19: HDR2.45 U1.19 | length 82.7
  Top Layer w0.2: v1(32.5,8.15) 32.5,7.075 36.475,3.1 58.15,3.1 64.925,9.875 64.925,25.146 61.096,28.975 59.597,28.975 55,33.572 55,36.441 54.525,36.916 54.525,41.191 53.35,42.366 v1(53.35,43.05)
  Bottom Layer w0.2: v1(32.5,8.15) HDR2.45@32.5,9.7 ; U1.19@49.4,42.251 51.351,42.251 52.175,43.075 53.325,43.075 v1(53.35,43.05)
IO20: HDR2.47 U1.20 | length 79.6
  Top Layer w0.2: v1(33.3,7.35) 33.3,7.275 37.075,3.5 57.975,3.5 64.525,10.05 64.525,23.481 64.525,24.981 60.931,28.575 59.431,28.575 59.078,28.928 54.6,33.406 54.6,36.275 54.125,36.75 54.125,41.025 52.825,42.325 v1(52.5,42.325)
  Bottom Layer w0.2: v1(33.3,7.35) HDR2.47@33.3,9.7 ; U1.20@49.4,41.751 51.926,41.751 v1(52.5,42.325)
IO21: HDR2.49 U1.21 | length 76.6
  Top Layer w0.2: v1(34.1,8.125) 34.1,7.05 37.25,3.9 57.8,3.9 64.125,10.225 64.125,24.815 60.765,28.175 59.266,28.175 54.2,33.241 54.2,36.091 53.725,36.566 53.725,40.35 v1(52.824,41.251)
  Bottom Layer w0.2: v1(34.1,8.125) HDR2.49@34.1,9.7 ; U1.21@49.4,41.251 v1(52.824,41.251)
IO22: HDR2.51 U1.23 | length 73.4
  Top Layer w0.2: v1(34.9,7.325) 34.9,7.25 37.85,4.3 57.625,4.3 63.725,10.4 63.725,24.649 60.599,27.775 59.1,27.775 53.8,33.075 53.8,35.925 53.325,36.4 53.325,39.278 v1(52.351,40.251)
  Bottom Layer w0.2: v1(34.9,7.325) HDR2.51@34.9,9.7 ; U1.23@49.4,40.251 v1(52.351,40.251)
IO23: HDR2.53 U1.31 | length 56
  Top Layer w0.2: v1(35.7,8.1) 35.7,7.05 36.175,6.575 36.175,6.541 37.616,5.1 39.225,5.1 40.075,5.95 43.125,5.95 43.75,6.575 51.494,6.575 51.569,6.5 53.125,6.5 54.25,7.625 54.25,21.85 53.4,22.7 53.4,35.525 v1@52.35,36.575
  Bottom Layer w0.2: v1(35.7,8.1) HDR2.53@35.7,9.7 ; U1.31@49.4,36.251 50.608,36.251 50.707,36.35 v1(52.5,36.35)
IO24: HDR2.55 U1.32 | length 53.3
  Top Layer w0.2: v1(36.5,7.325) 36.5,6.816 37.263,6.053 37.816,5.5 39.059,5.5 39.909,6.35 42.959,6.35 43.584,6.975 51.659,6.975 51.734,6.9 52.95,6.9 53.85,7.8 53.85,21.675 53,22.525 53,34.85 v1(52.65,35.2)
  Bottom Layer w0.2: v1(36.5,7.325) HDR2.55@36.5,9.7 ; U1.32@49.4,35.751 50.674,35.751 50.847,35.925 51.725,35.925 52.45,35.2 v1(52.65,35.2)
IO25: HDR2.57 U1.33 | length 50.9
  Top Layer w0.2: v1(37.3,8.1) 37.3,6.581 37.981,5.9 38.894,5.9 39.744,6.75 42.794,6.75 43.419,7.375 51.825,7.375 51.9,7.3 52.775,7.3 53.45,7.975 53.45,21.509 52.6,22.359 52.6,34.175 51.978,34.797 51.703,34.797 51.4,35.1 v1(51.4,35.175)
  Bottom Layer w0.2: v1(37.3,8.1) HDR2.57@37.3,9.7 ; U1.33@49.4,35.251 51.476,35.251 v1@51.558,35.169
IO26: HDR2.59 U1.34 | length 70.1
  Bottom Layer w0.2: HDR2.59@38.1,9.7 38.1,8.65 45.725,1.025 58.9,1.025 66.9,9.025 66.9,16.475 58.825,24.55 58.825,26.675 51.74,33.76 50.749,34.751 U1.34@49.4,34.751
IO27: HDR2.61 U1.35 | length 67.8
  Bottom Layer w0.2: HDR2.61@38.9,9.7 38.9,8.625 46.1,1.425 58.725,1.425 66.5,9.2 66.5,16.291 58.425,24.366 58.425,26.491 50.664,34.251 U1.35@49.4,34.251
IO28: HDR2.63 U1.37 | length 65.2
  Bottom Layer w0.2: HDR2.63@39.7,9.7 39.7,8.65 46.525,1.825 58.55,1.825 66.1,9.375 66.1,16.125 58.025,24.2 58.025,26.325 51.099,33.251 U1.37@49.4,33.251
IO29: HDR2.65 U1.38 | length 62.9
  Bottom Layer w0.2: HDR2.65@40.5,9.7 40.5,8.6 46.875,2.225 58.375,2.225 65.7,9.55 65.7,15.941 57.625,24.016 57.625,26.15 51.955,31.82 ; U1.38@49.4,32.751 51.033,32.751 51.959,31.825
IO30: HDR2.67 U1.39 | length 60.5
  Bottom Layer w0.2: HDR2.67@41.3,9.7 41.3,8.7 47.375,2.625 58.2,2.625 65.3,9.725 65.3,15.775 57.225,23.85 57.225,25.975 51.98,31.22 ; U1.39@49.4,32.251 50.958,32.251 51.984,31.225
IO31: HDR2.69 U1.42 | length 57.7
  Bottom Layer w0.2: HDR2.69@42.1,9.7 42.1,8.65 47.725,3.025 58.025,3.025 64.9,9.9 64.9,15.591 56.825,23.666 56.825,25.8 51.874,30.751 U1.42@49.4,30.751
IO32: HDR2.71 U1.43 | length 55.4
  Bottom Layer w0.2: HDR2.71@42.9,9.7 42.9,8.675 48.15,3.425 57.85,3.425 64.5,10.075 64.5,15.425 56.425,23.5 56.425,25.625 51.799,30.251 U1.43@49.4,30.251
IO33: HDR2.73 U1.44 | length 53.1
  Bottom Layer w0.2: HDR2.73@43.7,9.7 43.7,8.65 48.525,3.825 57.675,3.825 64.1,10.25 64.1,15.241 56.025,23.316 56.025,25.45 51.724,29.751 U1.44@49.4,29.751
IO34: HDR2.75 U1.45 | length 50.7
  Bottom Layer w0.2: HDR2.75@44.5,9.7 44.5,8.675 48.95,4.225 57.5,4.225 63.7,10.425 63.7,15.075 55.625,23.15 55.625,25.275 51.649,29.251 U1.45@49.4,29.251
IO35: HDR2.77 U1.46 | length 44.6
  Bottom Layer w0.2: HDR2.77@45.3,9.7 45.3,8.65 49.325,4.625 56.95,4.625 58.975,6.65 58.975,10.585 57.75,11.81 57.75,20.459 55.225,22.984 55.225,25.1 52.404,27.921 51.574,28.751 U1.46@49.4,28.751
JIOA0: HDR1.3 U1.155 | length 12
  Bottom Layer w0.2: HDR1.3@15.7,60.5 15.7,57.425 17.669,55.456 17.669,51.606 18.525,50.75 U1.155@19.575,50.75
JIOA1: HDR1.5 U1.158 | length 9.7
  Bottom Layer w0.2: HDR1.5@16.5,60.5 16.5,59.675 17.8,58.375 18.275,58.375 22.25,54.4 U1.158@22.25,53.425
JIOA2: HDR1.7 U1.159 | length 9.5
  Bottom Layer w0.2: HDR1.7@17.3,60.5 17.3,59.625 18.15,58.775 18.45,58.775 22.75,54.475 U1.159@22.75,53.425
JIOA3: HDR1.9 U1.160 | length 9.3
  Bottom Layer w0.2: HDR1.9@18.1,60.5 18.1,59.525 18.45,59.175 18.625,59.175 23.25,54.55 U1.160@23.25,53.425
JIOB0: HDR1.83 U1.204 | length 8.1
  Bottom Layer w0.2: U1.204@45.25,53.425 45.25,55.85 47.7,58.3 HDR1.83@47.7,60.5
JIOB1: HDR1.85 U1.205 | length 8.2
  Bottom Layer w0.2: U1.205@45.75,53.425 45.75,55.784 48.5,58.534 HDR1.85@48.5,60.5
JIOB2: HDR1.87 U1.206 | length 8.3
  Bottom Layer w0.2: U1.206@46.25,53.425 46.25,55.719 49.3,58.769 HDR1.87@49.3,60.5
JIOB3: HDR1.89 U1.207 | length 8.5
  Bottom Layer w0.2: U1.207@46.75,53.425 46.75,55.653 50.1,59.003 HDR1.89@50.1,60.5
KBCLOCK: HDR1.22 U1.144 | length 51.9
  Bottom Layer w0.2: U1.144@19.575,45.25 17.575,45.25 14.025,48.8 14.016,48.8 13.269,49.546 13.269,52.081 4.425,60.925 4.425,66.025 10.675,72.275 18.9,72.275 22.9,68.275 HDR1.22@22.9,67.3
KBDATA: HDR1.24 U1.143 | length 54.3
  Bottom Layer w0.2: U1.143@19.575,44.75 17.5,44.75 12.869,49.381 12.869,51.906 4.025,60.75 4.025,66.2 10.5,72.675 19.375,72.675 23.7,68.35 HDR1.24@23.7,67.3
LCD_BCKL: HDR2.22 U1.92 | length 9.1
  Bottom Layer w0.2: HDR2.22@22.9,16.5 22.9,17.55 27.75,22.4 U1.92@27.75,23.575
LCD_E: HDR2.26 U1.90 | length 8.8
  Bottom Layer w0.2: HDR2.26@24.5,16.5 24.5,18.009 28.75,22.259 U1.90@28.75,23.575
LED0: HDR2.60 U1.68 | length 7.8
  Bottom Layer w0.2: HDR2.60@38.1,16.5 38.1,20.75 39.75,22.4 U1.68@39.75,23.575
LED1: HDR2.62 U1.67 | length 7.6
  Bottom Layer w0.2: HDR2.62@38.9,16.5 38.9,20.984 40.25,22.334 U1.67@40.25,23.575
LED2: HDR2.64 U1.66 | length 7.5
  Bottom Layer w0.2: HDR2.64@39.7,16.5 39.7,21.175 40.75,22.225 U1.66@40.75,23.575
LED3: HDR2.66 U1.64 | length 7.6
  Bottom Layer w0.2: HDR2.66@40.5,16.5 40.5,21.409 41.75,22.659 U1.64@41.75,23.575
LED4: HDR2.68 U1.63 | length 7.5
  Bottom Layer w0.2: HDR2.68@41.3,16.5 41.3,21.625 42.25,22.575 U1.63@42.25,23.575
LED5: HDR2.70 U1.62 | length 7.3
  Bottom Layer w0.2: HDR2.70@42.1,16.5 42.1,21.859 42.75,22.509 U1.62@42.75,23.575
LED6: HDR2.72 U1.61 | length 7.2
  Bottom Layer w0.2: HDR2.72@42.9,16.5 42.9,22.094 43.25,22.444 U1.61@43.25,23.575
LED7: HDR2.74 U1.60 | length 7.1
  Bottom Layer w0.2: HDR2.74@43.7,16.5 43.7,22.3 43.75,22.35 U1.60@43.75,23.575
MOUSECLOCK: HDR1.26 U1.140 | length 57
  Bottom Layer w0.2: U1.140@19.575,43.25 18.425,43.25 13.611,48.064 13.611,48.074 12.469,49.215 12.469,51.731 3.625,60.575 3.625,66.375 10.325,73.075 19.7,73.075 24.5,68.275 HDR1.26@24.5,67.3
MOUSEDATA: HDR1.28 U1.139 | length 59.4
  Bottom Layer w0.2: U1.139@19.575,42.75 18.35,42.75 12.069,49.031 12.069,51.556 3.225,60.4 3.225,66.55 10.15,73.475 20.125,73.475 25.3,68.3 HDR1.28@25.3,67.3
NetC27_2: C27.2 R6.1 R7.1 R8.2 U2.3 | length 17.5
  Top Layer w0.2: C27.2@2.622,44.322 C27.2@2.625,44.322 ; v1@5.6,40.125 v1(5.65,40.175) ; U2.3@9.15,47.5 v1(9.925,47.5)
  Top Layer w0.25: R8.2@2.625,42.122 2.653,42.122 R7.1@4.525,40.25
  Top Layer w0.5: R8.2@2.625,42.122 C27.2@2.625,44.322 ; R7.1@4.525,39.922 5.397,39.922 v1(5.65,40.175) 5.925,40.45 R6.1@7.003,40.45
  Bottom Layer w0.2: v1(5.65,40.175) 5.65,43.225 v1(9.925,47.5)
NetC32_1: C32.1 L2.2 U3.1 | length 6.3
  Top Layer w0.5: C32.1@62.1,40.1 U3.1@64.75,40.1
  Top Layer w1: C32.1@62.1,40.1 62.65,39.55 L2.2@62.65,36.7
NetC32_2: C32.2 D2.1 L3.1 | length 7.4
  Top Layer w1: L3.1@58.75,42.55 61.35,42.55 62.3,43.5 D2.1@62.3,45.5 ; C32.2@59.3,40.1 59.3,41.55
NetC37_2: C37.2 R9.1 R10.1 R11.2 U3.3 | length 22.5
  Top Layer w0.2: v1(63.275,52.7) R10.1@63.275,54.078 ; U3.3@66.65,40.1 66.95,39.8 v1(67.45,39.8)
  Top Layer w0.5: R11.2@61.65,54.078 63.275,54.078 R10.1@63.3,54.103 R9.1@63.3,56.403 C37.2@61.7,56.403
  Bottom Layer w0.2: v1(63.275,52.7) 66.7,49.275 66.7,40.55 v1(67.45,39.8)
NetD1_1: D1.1 L1.2 U2.1 | length 6.4
  Top Layer w0.5: L1.2@3.5,46.55 6.025,46.55 6.975,47.5 U2.1@7.25,47.5 ; D1.1@6.25,44.5 6.25,46.775
NetLED1_1: LED1.1 R14.1 | length 8.6
  Top Layer w0.25: LED1.1@18.557,5.512 18.557,4.818 19,4.375 21.275,4.375 21.525,4.625 21.525,7.15 22.475,8.1 R14.1@23.247,8.1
